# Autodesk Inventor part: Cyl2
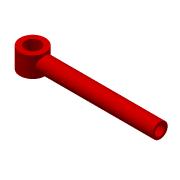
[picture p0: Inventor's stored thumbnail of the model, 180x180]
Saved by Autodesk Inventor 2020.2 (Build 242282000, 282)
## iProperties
Created: 2005-10
Part Number: Cyl2
Document SubType Name: Modeling
Designer: F.Stasiak
Density: 1 g/cm^3
Material: Ogólny
Appearance: Czerwony
Manager: www.cadconsulting.pl
Company: Fabian Stasiak CAD Consulting
Author: F.Stasiak
Subject: Zbiór ćwiczeń. Autodesk Inventor 2020. Kurs podstawowy
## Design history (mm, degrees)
sketch "Szkic1"
  geometry: L1 (6.669, 0)-(506.669, 0); L2 (506.669, 0)-(506.669, 30); L3 (506.669, 30)-(6.669, 30); L4 (6.669, 30)-(6.669, 0); C1 r 50 at (6.669, 30); 2 further points
  constraints: 8 end point, 2 coincident, 2 parallel, 1 centre point, 1 horizontal, 1 perpendicular, 1 vertical alignment, 2 other
  dimensions: "d0" = 500 distance of L1.start L1.end; "d1" = 30 distance of L1.end L2.end; "d2" = 100 diameter of C1
revolve "Obrót1" stored, may be unused: angle "d3" = 90 deg
extrude "Wyciągnięcie proste1" join sketch "Szkic1" stored distance "d4" = 80; taper "d5" = 0 deg
extrude "Wyciągnięcie proste2" cut sketch "Szkic1" extent not by distance; stored distance "d6" = 80; taper "d7" = 0 deg
sketch "Szkic2"
  geometry: C1 r 30 at (0, 0) reference; C2 r 20 at (0, 0)
  constraints: 1 centre point, 1 coincident
  dimensions: "d8" = 40 diameter of C2
extrude "Wyciągnięcie proste3" cut sketch "Szkic2" distance "d9" = 400; taper "d10" = 0 deg
node "Bryła1"
node "Korpusy bryłowe"
node "Korpusy powierzchniowe"
